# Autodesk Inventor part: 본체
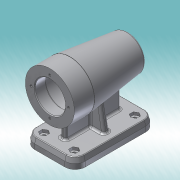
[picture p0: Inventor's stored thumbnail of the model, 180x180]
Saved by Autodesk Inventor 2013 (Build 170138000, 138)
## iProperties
Created: 2017-01
Part Number: 본체
Material: 알루미늄 6061
Document SubType Name: Modeling
Designer: dgall
Density: 2.71 g/cm^3
Mass: 795.03 g
Surface Area: 661.674 cm^2
Volume: 293.369 cm^3
Author: dgall
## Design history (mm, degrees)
sketch "스케치3"
  geometry: L1 (56, 0)-(56, 34); L2 (56, 34)-(28, 34); L3 (28, 34)-(-52.27, 24.144); L4 (-56, 0)-(56, 0); A1 r 80 centre (24, 0) between (-52.27, 24.144) and (-56, 0); 2 further points
  constraints: 8 end point, 2 point on circle, 1 centre point, 1 midpoint, 1 parallel, 1 perpendicular, 1 point on line, 1 vertical, 1 vertical alignment
  dimensions: "d4" = 68 diameter of L2 L4; "d6" = 28 distance from line of L2.end L1; "d7" = 112 dimension on A1 L1; "d8" = 80 radius of A1; "d9" = 7 deg angle of L3 L2; "d10" = 56 distance from line of point (0, 0) L1
revolve "회전1" sketch "스케치3" stored, may be unused: angle "d11" = 90 deg
sketch "스케치4"
  geometry: L1 (-50, 0)-(-50, 10.5); L2 (-50, 10.5)-(-47, 10.5); L3 (-47, 10.5)-(-47, 16); L4 (-47, 16)-(-43, 16); L5 (-43, 16)-(-43, 17.5); L6 (-43, 17.5)-(-25, 17.5); L7 (-25, 17.5)-(-25, 21); L8 (-25, 21)-(-13, 21); L9 (-13, 21)-(-13, 24); L10 (-13, 24)-(41, 24); L11 (41, 24)-(41, 21); L12 (41, 21)-(56, 21); L13 (56, 21)-(56, 0); L14 (56, 0)-(-50, 0); L15 (56, -34)-(56, 34) reference; 2 further points
  constraints: 28 end point, 12 parallel, 2 point on line, 1 midpoint, 1 perpendicular, 1 vertical
  dimensions: "d12" = 15 distance between parallel lines of L13 L11; "d14" = 54 distance between parallel lines of L11 L9; "d15" = 12 distance between parallel lines of L9 L7; "d16" = 18 distance between parallel lines of L7 L5; "d17" = 4 distance between parallel lines of L5 L3; "d18" = 3 distance between parallel lines of L3 L1; "d19" = 21 diameter of L2 L14; "d20" = 32 diameter of L4 L14; "d21" = 35 diameter of L6 L14; "d22" = 42 diameter of L8 L14; "d23" = 48 diameter of L10 L14; "d24" = 42 diameter of L12 L14
revolve "회전2" sketch "스케치4" stored, may be unused: angle "d25" = 90 deg
node "작업 평면2"
  node "작업 평면1"
sketch "스케치9"
  geometry: L1 (-21, -56)-(21, -56); L2 (35, -42)-(35, 42); L3 (21, 56)-(-21, 56); L4 (-35, 42)-(-35, -42); L5 (-35, -56)-(35, 56); L6 (35, -56)-(-35, 56); A1 r 14 centre (-21, 42) between (-21, 56) and (-35, 42); A2 r 14 centre (21, 42) between (35, 42) and (21, 56); A3 r 14 centre (21, -42) between (21, -56) and (35, -42); A4 r 14 centre (-21, -42) between (-35, -42) and (-21, -56); 1 further point
  constraints: 12 end point, 8 point on circle, 8 point on line, 8 tangent, 4 centre point, 2 equal radius, 2 midpoint, 2 parallel, 1 horizontal, 1 perpendicular
  dimensions: "d136" = 70 distance of L5.end L6.end; "d137" = 112 distance of L6.start L5.end; "d138" = 14 radius of A1; "d139" = 14 radius of A2
extrude "돌출5" join sketch "스케치9" distance "d64" = 7; taper "d65" = -15 deg
sketch "스케치10"
  geometry: L1 (-21, 56)-(21, 56); L2 (35, 42)-(35, -42); L3 (21, -56)-(-21, -56); L4 (-35, -42)-(-35, 42); A1 r 14 centre (-21, 42) between (-21, 56) and (-35, 42); A2 r 14 centre (21, 42) between (35, 42) and (21, 56); A3 r 14 centre (21, -42) between (21, -56) and (35, -42); A4 r 14 centre (-21, -42) between (-35, -42) and (-21, -56); 5 further points
  constraints: 8 end point, 8 point on circle, 8 point on line, 8 tangent, 4 centre point, 3 equal radius, 2 parallel, 1 horizontal, 1 perpendicular
  dimensions: "d67" = 70 distance of point (-35, 56) point (35, 56); "d69" = 112 distance of point (-35, -56) point (-35, 56); "d70" = 35 distance from line of L4 point (0, 0); "d71" = 56 distance from line of L3 point (0, 0); "d140" = 14 radius of A1
extrude "돌출6" join sketch "스케치10" distance "d72" = 7; taper "d73" = 0 deg
sketch "스케치12"
  geometry: 2 further points
  dimensions: "d96" = 21 horizontal distance of point (21, -41) point (0, 0); "d97" = 41 vertical distance of point (21, -41) point (0, 0)
sketch "스케치7"
  geometry: C1 r 21 at (0, 0) reference; 1 further point
  constraints: 1 vertical alignment
  dimensions: "d45" = 26 distance of point (0, 26) C1.centre
hole "구멍1" sketch "스케치7" at (0, 26) diameter "d46" = 3.242; stored, may be unused: countersink angle "d50" = 90 deg, drill point angle "d52" = 118 deg; dims "d47" = 8, "d48" = 4, "d49" = 2, "d51" = 11
sketch "스케치11"
  geometry: L1 (-4, 38)-(4, 38); L2 (4, 38)-(4, -38); L3 (4, -38)-(-4, -38); L4 (-4, -38)-(-4, 38); L5 (-23, 4)-(23, 4); L6 (23, 4)-(23, -4); L7 (23, -4)-(-23, -4); L8 (-23, -4)-(-23, 4); L9 (-21, 56)-(21, 56) reference; L10 (-35, -42)-(-35, 42) reference; L11 (21, -56)-(-21, -56) reference; L12 (35, 42)-(35, -42) reference; 1 further point
  constraints: 16 end point, 4 parallel, 2 horizontal, 2 perpendicular
  dimensions: "d74" = 8 distance between parallel lines of L7 L5; "d76" = 8 distance between parallel lines of L2 L4; "d81" = 4 distance from line of L5 point (0, 0); "d82" = 4 distance from line of L2 point (0, 0); "d141" = 18 distance between parallel lines of L1 L9; "d142" = 18 distance between parallel lines of L11 L3; "d143" = 12 distance between parallel lines of L6 L12; "d144" = 12 distance between parallel lines of L10 L8
extrude "돌출7" join sketch "스케치11" stored distance "d83" = 7; taper "d84" = 0 deg
feature "면 기울기4" dims angle "d85" = 10 deg
fillet "모깎기3" dims "d88" = 0.3
fillet "모깎기4" dims "d89" = 3
chamfer "모따기1" distance "d90" = 1; stored, may be unused: second distance "d91" = 2, angle "d92" = 45 deg
fillet "모깎기5" dims "d93" = 3
hole "구멍2" sketch "스케치12" diameter "d98" = 5; stored, may be unused: countersink angle "d102" = 90 deg, drill point angle "d104" = 0 deg; dims "d99" = 8, "d100" = 10, "d101" = 4, "d103" = 14
sketch "스케치13"
  geometry: L1 (21, -35.226)-(26, -38.113); L2 (26, -38.113)-(26, -43.887); L3 (26, -43.887)-(21, -46.774); L4 (21, -46.774)-(16, -43.887); L5 (16, -43.887)-(16, -38.113); L6 (16, -38.113)-(21, -35.226); 4 further points
  constraints: 12 end point, 1 coincident, 1 midpoint, 1 vertical alignment, 15 other
extrude "돌출8" cut sketch "스케치13" distance "d105" = 4; taper "d106" = 0 deg
fillet "모깎기8" dims "d113" = 3
sketch "스케치14"
  geometry: L1 (0, 84)-(0, 0) reference; L2 (0, 98)-(-7, 98) reference; 2 further points
  constraints: 1 other
  dimensions: "d151" = 56 distance from line of L2 point (-4, 42); "d152" = 4 distance from line of point (-4, 42) L1
feature "엠보싱1" sketch "스케치14" dims "d4" = 68, "d6" = 28, "d7" = 112, "d8" = 80, "d9" = 7 deg, "d10" = 56, "d116" = 0.5, "d117" = 0
fillet "모깎기9" dims "d118" = 3
fillet "모깎기10" dims "d119" = 3
fillet "모깎기12" dims "d121" = 3
fillet "모깎기15" dims "d153" = 1
node "솔리드2"
pattern_circular "원형 패턴1" dims angle "d54" = 360 deg
pattern_linear "직사각형 패턴2" dims "d147" = 84, "d150" = 42
other parameters: "d26" = 74, "d59" = -7
